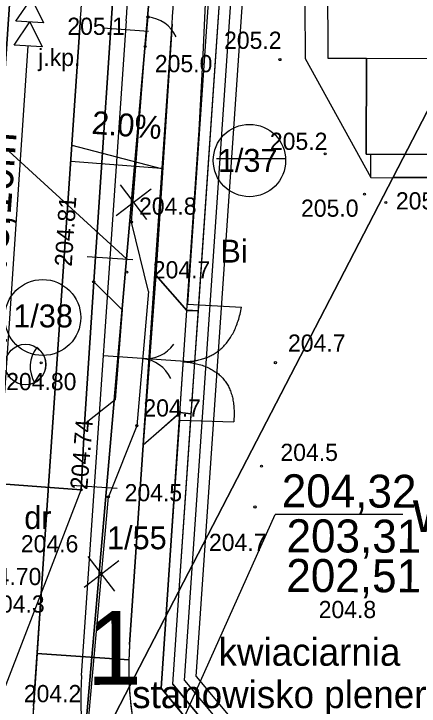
# Model space of a CAD drawing. Extents: x 6512606 to 6513006, y 6022524 to 6022728.
# Drawn here: x 6512732.82 to 6512750.51, y 6022610.86 to 6022641.08 of the extents above; entities that cross this region are included whole.
import ezdxf

# ---------------------------------------------------------------- set-up
doc = ezdxf.new("R2010")
doc.units = 0
for name, color, linetype in [('20', 7, 'Continuous'), ('210-oznaczenie konturu użytku gruntowego', 7, 'Continuous'), ('211-numer działki ewidencyjnej', 7, 'Continuous'), ('217-kontur klasyfikacyjny', 7, 'Continuous'), ('218-kontur użytku gruntowego', 7, 'Continuous'), ('219-działka ewidencyjna', 7, 'Continuous'), ('3', 7, 'Continuous'), ('312-budynek ewidencyjny', 7, 'Continuous'), ('320-blok - kondygnacja nadziemna', 7, 'Continuous'), ('4', 7, 'Continuous'), ('6', 7, 'Continuous'), ('brama (linia)', 7, 'Continuous'), ('brama (linia) - symbol', 7, 'Continuous'), ('Default', 7, 'Continuous'), ('E_OSW_LAMPA', 7, 'Continuous'), ('furtka', 7, 'Continuous'), ('jezdnia', 7, 'Continuous'), ('jezdnia (powierzchnia)', 7, 'Continuous'), ('jezdnia (powierzchnia)-Atr17', 7, 'Continuous'), ('kolor_kostka_bet', 7, 'Continuous'), ('kolor_sc_rowerowa', 7, 'Continuous'), ('Komentarz lub etykieta na mapie', 7, 'Continuous'), ('krawężnik (linia)', 7, 'Continuous'), ('Level 47', 7, 'Continuous'), ('Level 60', 7, 'Continuous'), ('maxp_kan_deszczowa', 7, 'Continuous'), ('maxp_kraw_obniżony', 7, 'Continuous'), ('maxp_krawężnik', 7, 'Continuous'), ('maxp_likwidacje', 7, 'Continuous'), ('maxp_opornik', 7, 'Continuous'), ('maxp_os', 7, 'Continuous'), ('maxp_przechyłki', 7, 'Continuous'), ('maxp_ramka_2', 7, 'Continuous'), ('ogrodzenie', 7, 'Continuous'), ('ogrodzenie trwałe', 7, 'Continuous'), ('ogrodzenie trwałe (linia)', 7, 'Continuous'), ('pikieta naturalna', 7, 'Continuous'), ('pikieta naturalna-Atr2', 7, 'Continuous'), ('pikieta sztuczna', 7, 'Continuous'), ('pikieta sztuczna-Atr2', 7, 'Continuous'), ('przewód kanalizacyjny (linia)', 7, 'Continuous'), ('punkt wysokościowy naturalny', 7, 'Continuous'), ('punkt wysokościowy naturalny-Atr2', 7, 'Continuous'), ('punkt wysokościowy sztuczny', 7, 'Continuous'), ('punkt wysokościowy sztuczny-Atr2', 7, 'Continuous')]:
    doc.layers.add(name, color=color, linetype=linetype)

# ---------------------------------------------------------------- blocks, each defined once
blk = doc.blocks.new('PW01')
at = {"layer": 'Default'}
blk.add_circle((0, 0), 0.45, dxfattribs=at)
blk = doc.blocks.new('OK02')
at = {"layer": 'Default'}
for centre, start, end in [((-15, 0), 0, 60), ((15, 0), 120, 180)]:
    blk.add_arc(centre, 15, start, end, dxfattribs=at)
blk = doc.blocks.new('PW02')
at = {"layer": 'Default'}
blk.add_circle((0, 0), 0.45, dxfattribs=at)
blk = doc.blocks.new('OK04')
at = {"layer": 'Default'}
blk.add_arc((15, 0.01), 15, 120, 180, dxfattribs=at)

msp = doc.modelspace()

# ---------------------------------------------------------------- linework, layer by layer
for p, q in [((6512740.034, 6022615.911), (6512743.337, 6022664.192)), ((6512739.753, 6022611.813), (6512740.034, 6022615.911)), ((6512739.753, 6022611.813), (6512749.181, 6022600.515))]:
    msp.add_line(p, q)
at = {"layer": '20'}
for p in [(6512738.693, 6022606.882), (6512749.792, 6022619.226)]:
    msp.add_line(p, (6512744.215, 6022619.226), dxfattribs=at)
at = {"layer": '217-kontur klasyfikacyjny'}
for points in [[(6512749.37, 6022633.95), (6512735.75, 6022607.64)], [(6512762.09, 6022633.91), (6512749.37, 6022633.95)]]:
    msp.add_lwpolyline(points, dxfattribs=at)
at = {"layer": '218-kontur użytku gruntowego'}
for points in [[(6512739.15, 6022646.62), (6512737.73, 6022630.38)], [(6512737.73, 6022630.38), (6512739.15, 6022646.62)], [(6512749.37, 6022633.95), (6512751.92, 6022638.86)], [(6512751.92, 6022638.86), (6512749.37, 6022633.95)], [(6512731.57, 6022636.01), (6512737.73, 6022630.38)], [(6512737.73, 6022630.38), (6512731.57, 6022636.01)], [(6512735.75, 6022607.64), (6512749.37, 6022633.95)], [(6512749.37, 6022633.95), (6512735.75, 6022607.64)], [(6512762.09, 6022633.91), (6512749.37, 6022633.95)], [(6512749.37, 6022633.95), (6512762.09, 6022633.91)], [(6512737.73, 6022630.38), (6512735.75, 6022607.64)], [(6512735.75, 6022607.64), (6512737.73, 6022630.38)]]:
    msp.add_lwpolyline(points, dxfattribs=at)
at = {"layer": '219-działka ewidencyjna'}
for points in [[(6512739.15, 6022646.62), (6512735.75, 6022607.64)], [(6512751.92, 6022638.86), (6512735.75, 6022607.64)]]:
    msp.add_lwpolyline(points, dxfattribs=at)
at = {"layer": '3'}
msp.add_line((6512741.658, 6022634.756), (6512744.697, 6022634.756), dxfattribs=at)
at = {"layer": '312-budynek ewidencyjny'}
for points in [[(6512746.53, 6022639.13), (6512746.45, 6022659.51)], [(6512748.21, 6022639.13), (6512746.53, 6022639.13)], [(6512748.2, 6022634.95), (6512748.21, 6022639.13)], [(6512759.3, 6022634.91), (6512748.2, 6022634.95)]]:
    msp.add_lwpolyline(points, dxfattribs=at)
at = {"layer": '320-blok - kondygnacja nadziemna'}
msp.add_lwpolyline([(6512759.31, 6022639.09), (6512748.21, 6022639.13), (6512748.2, 6022634.95), (6512759.3, 6022634.91)], close=True, dxfattribs=at)
at = {"layer": '4'}
for points in [[(6512739.15, 6022646.62), (6512735.75, 6022607.64)], [(6512751.92, 6022638.86), (6512735.75, 6022607.64)]]:
    msp.add_lwpolyline(points, dxfattribs=at)
at = {"layer": '6'}
for centre, radius in [((6512743.099, 6022634.675), 1.579), ((6512734.076, 6022627.821), 1.659)]:
    msp.add_circle(centre, radius, dxfattribs=at)
at = {"layer": 'brama (linia)'}
msp.add_lwpolyline([(6512738.69, 6022628.95), (6512738.18, 6022623.1)], dxfattribs=at)
at = {"layer": 'E_OSW_LAMPA'}
msp.add_circle((6512733.326, 6022625.771), 0.885, dxfattribs=at)
for centre, radius, start, end in [((6512734.891, 6022625.665), 1.362, 141.9102, 210.3688), ((6512733.326, 6022625.771), 0.885, 296.1395, 56.1395)]:
    msp.add_arc(centre, radius, start, end, dxfattribs=at)
at = {"layer": 'furtka'}
msp.add_lwpolyline([(6512738.67, 6022640.94), (6512738.55, 6022639.65)], dxfattribs=at)
at = {"layer": 'jezdnia'}
msp.add_lwpolyline([(6512731.08, 6022620.65), (6512728.82, 6022611.46), (6512722.83, 6022600.42), (6512717.94, 6022592.02), (6512712.43, 6022580.37), (6512709.04, 6022573), (6512712.21, 6022570.83), (6512715.01, 6022579.3), (6512720.33, 6022590.74), (6512725.35, 6022598.98), (6512731.85, 6022610.22), (6512735.75, 6022620.3)], close=True, dxfattribs=at)
at = {"layer": 'jezdnia (powierzchnia)'}
msp.add_lwpolyline([(6512732.9, 6022645.58), (6512731.83, 6022629.89), (6512731.08, 6022620.65), (6512735.75, 6022620.3), (6512735.9, 6022623.16), (6512736.3, 6022629.38), (6512737.37, 6022645.25)], dxfattribs=at)
at = {"layer": 'kolor_kostka_bet'}
for p, q in [((6512740.868, 6022628.114), (6512743.337, 6022664.192)), ((6512739.008, 6022629.668), (6512739.72, 6022640.633)), ((6512739.72, 6022640.633), (6512739.008, 6022629.668)), ((6512738.462, 6022622.246), (6512739.008, 6022629.668)), ((6512739.008, 6022629.668), (6512738.462, 6022622.246)), ((6512740.368, 6022628.13), (6512739.008, 6022629.668)), ((6512739.008, 6022629.668), (6512740.368, 6022628.13)), ((6512740.868, 6022628.114), (6512740.368, 6022628.13)), ((6512740.368, 6022628.13), (6512740.868, 6022628.114)), ((6512740.561, 6022623.624), (6512740.868, 6022628.114)), ((6512740.561, 6022623.624), (6512740.868, 6022628.114)), ((6512738.462, 6022622.246), (6512740.064, 6022623.676)), ((6512740.064, 6022623.676), (6512738.462, 6022622.246)), ((6512740.064, 6022623.676), (6512739.241, 6022611.647)), ((6512739.241, 6022611.647), (6512740.064, 6022623.676)), ((6512740.034, 6022615.911), (6512740.561, 6022623.624)), ((6512740.064, 6022623.676), (6512740.561, 6022623.624)), ((6512740.561, 6022623.624), (6512740.064, 6022623.676)), ((6512737.867, 6022613.542), (6512738.462, 6022622.246)), ((6512738.462, 6022622.246), (6512737.867, 6022613.542)), ((6512739.753, 6022611.813), (6512740.034, 6022615.911)), ((6512737.836, 6022612.876), (6512733.831, 6022613.149)), ((6512733.831, 6022613.149), (6512737.836, 6022612.876)), ((6512739.241, 6022611.647), (6512748.908, 6022600.062)), ((6512748.908, 6022600.062), (6512739.241, 6022611.647)), ((6512749.181, 6022600.515), (6512739.753, 6022611.813))]:
    msp.add_line(p, q, dxfattribs=at)
for points in [[(6512735.73, 6022640.906), (6512735.73, 6022640.906), (6512734.114, 6022617.289), (6512733.831, 6022613.149)], [(6512733.831, 6022613.149), (6512733.712, 6022611.416), (6512733.674, 6022610.856)]]:
    msp.add_lwpolyline(points, dxfattribs=at)
for centre, radius, start, end in [((6512687.841, 6022644.182), 48, 356.0866, 2.076), ((6512687.841, 6022644.182), 52, 356.0865, 2.076), ((6512687.841, 6022644.182), 52, 356.0868, 2.076), ((6512752.832, 6022612.518), 15, 176.0865, 257.9783), ((6512752.832, 6022612.518), 15, 176.0865, 178.633), ((6512752.832, 6022612.518), 15, 178.633, 257.9783), ((6512748.639, 6022609.832), 15, 176.0865, 257.9783)]:
    msp.add_arc(centre, radius, start, end, dxfattribs=at)
at = {"layer": 'kolor_sc_rowerowa'}
msp.add_lwpolyline([(6512733.674, 6022610.856), (6512733.712, 6022611.416), (6512733.831, 6022613.149), (6512734.114, 6022617.289), (6512735.73, 6022640.906), (6512735.73, 6022640.906)], dxfattribs=at)
for centre, radius, start, end in [((6512687.841, 6022644.182), 48, 356.0866, 2.076), ((6512748.639, 6022609.832), 15, 176.0865, 185.7922)]:
    msp.add_arc(centre, radius, start, end, dxfattribs=at)
at = {"layer": 'krawężnik (linia)'}
msp.add_lwpolyline([(6512737.37, 6022645.25), (6512736.3, 6022629.38), (6512735.9, 6022623.16), (6512735.75, 6022620.3), (6512731.08, 6022620.65), (6512731.83, 6022629.89), (6512732.9, 6022645.58)], dxfattribs=at)
msp.add_lwpolyline([(6512736.3, 6022629.38), (6512737.54, 6022628.16), (6512737.24, 6022624.23), (6512735.9, 6022623.16)], close=True, dxfattribs=at)
at = {"layer": 'Level 60'}
for points in [[(6512738.696, 6022640.31), (6512736.7, 6022640.447)], [(6512738.013, 6022630.334), (6512736.018, 6022630.47)], [(6512737.331, 6022620.357), (6512735.335, 6022620.493)]]:
    msp.add_lwpolyline(points, dxfattribs=at)
at = {"layer": 'maxp_kan_deszczowa'}
for p, q in [((6512733.512, 6022640.721), (6512733.512, 6022640.722)), ((6512732.109, 6022620.216), (6512733.44, 6022639.674))]:
    msp.add_line(p, q, dxfattribs=at)
msp.add_lwpolyline([(6512748.908, 6022600.062), (6512739.241, 6022611.647), (6512740.368, 6022628.13), (6512740.906, 6022635.995), (6512741.065, 6022638.988), (6512741.55, 6022649.49)], dxfattribs=at)
for points in [[(6512732.907, 6022640.763), (6512733.583, 6022641.769), (6512734.116, 6022640.68)], [(6512732.835, 6022639.716), (6512733.512, 6022640.722), (6512734.045, 6022639.633)]]:
    msp.add_lwpolyline(points, close=True, dxfattribs=at)
at = {"layer": 'maxp_kraw_obniżony'}
msp.add_line((6512738.462, 6022622.246), (6512738.974, 6022629.728), dxfattribs=at)
at = {"layer": 'maxp_krawężnik'}
for p, q in [((6512733.674, 6022610.856), (6512735.73, 6022640.906)), ((6512738.974, 6022629.728), (6512739.72, 6022640.633)), ((6512737.867, 6022613.542), (6512738.462, 6022622.246))]:
    msp.add_line(p, q, dxfattribs=at)
for centre, radius, start, end in [((6512687.841, 6022644.182), 48, 356.0865, 2.076), ((6512687.841, 6022644.182), 52, 356.0865, 2.076), ((6512752.832, 6022612.518), 15, 176.0865, 257.9783), ((6512748.639, 6022609.832), 15, 176.0865, 228.4237)]:
    msp.add_arc(centre, radius, start, end, dxfattribs=at)
at = {"layer": 'maxp_likwidacje'}
for p, q in [((6512737.287, 6022632.277), (6512738.807, 6022633.432)), ((6512738.624, 6022632.094), (6512737.469, 6022633.614)), ((6512737.22, 6022615.872), (6512736.065, 6022617.392)), ((6512735.883, 6022616.055), (6512737.403, 6022617.21))]:
    msp.add_line(p, q, dxfattribs=at)
at = {"layer": 'maxp_opornik'}
for p, q in [((6512740.351, 6022628.149), (6512738.974, 6022629.728)), ((6512740.061, 6022623.64), (6512740.368, 6022628.13)), ((6512740.868, 6022628.114), (6512740.351, 6022628.149)), ((6512740.561, 6022623.624), (6512740.868, 6022628.114)), ((6512740.061, 6022623.64), (6512738.462, 6022622.246)), ((6512740.561, 6022623.624), (6512740.081, 6022623.657))]:
    msp.add_line(p, q, dxfattribs=at)
at = {"layer": 'maxp_os'}
for p, q in [((6512735.77, 6022612.199), (6512737.725, 6022640.769)), ((6512740.715, 6022625.869), (6512736.724, 6022626.142))]:
    msp.add_line(p, q, dxfattribs=at)
for centre, radius, start, end in [((6512687.841, 6022644.182), 50, 356.0868, 2.076), ((6512750.735, 6022611.175), 15, 176.0865, 257.9783)]:
    msp.add_arc(centre, radius, start, end, dxfattribs=at)
at = {"layer": 'maxp_przechyłki'}
msp.add_lwpolyline([(6512735.301, 6022634.639), (6512735.349, 6022635.349), (6512739.252, 6022634.323)], close=True, dxfattribs=at)
at = {"layer": 'maxp_ramka_2'}
for p, q in [((6512740.266, 6022611.979), (6512743.834, 6022664.131)), ((6512740.778, 6022612.146), (6512744.33, 6022664.055)), ((6512740.266, 6022611.979), (6512743.422, 6022658.115)), ((6512740.266, 6022611.979), (6512743.422, 6022658.115)), ((6512740.266, 6022611.979), (6512749.565, 6022600.835)), ((6512740.778, 6022612.146), (6512749.728, 6022601.421))]:
    msp.add_line(p, q, dxfattribs=at)
at = {"layer": 'ogrodzenie'}
for p, q in [((6512742.416, 6022658.054), (6512740.388, 6022628.41)), ((6512740.388, 6022628.41), (6512742.755, 6022628.271)), ((6512740.04, 6022623.334), (6512739.236, 6022611.581)), ((6512740.04, 6022623.334), (6512742.411, 6022623.27)), ((6512739.241, 6022611.647), (6512748.908, 6022600.062))]:
    msp.add_line(p, q, dxfattribs=at)
for points in [[(6512740.218, 6022625.897), (6512742.308, 6022625.904), (6512742.755, 6022628.271)], [(6512740.222, 6022625.892), (6512742.623, 6022625.677), (6512742.411, 6022623.27)]]:
    msp.add_open_spline(points, degree=2, dxfattribs=at)
at = {"layer": 'ogrodzenie trwałe'}
msp.add_lwpolyline([(6512755.94, 6022562.73), (6512746.11, 6022568.85), (6512734.85, 6022575.76), (6512722.94, 6022583.56), (6512729.52, 6022596.18), (6512735.87, 6022607.95), (6512736.94, 6022619.99)], dxfattribs=at)
at = {"layer": 'ogrodzenie trwałe (linia)'}
for points in [[(6512738.67, 6022640.94), (6512739.22, 6022646.99), (6512741.85, 6022657.91), (6512744.36, 6022658.55), (6512746.45, 6022659.08)], [(6512738.69, 6022628.95), (6512737.95, 6022631.99), (6512738.55, 6022639.65)], [(6512738.18, 6022623.1), (6512736.94, 6022619.99)]]:
    msp.add_lwpolyline(points, dxfattribs=at)
at = {"layer": 'przewód kanalizacyjny (linia)'}
for points in [[(6512750.63, 6022659.53), (6512750.53, 6022662.41), (6512746.52, 6022662.45), (6512746.43, 6022659.54), (6512745.45, 6022659.51), (6512745.46, 6022656.91), (6512745.52, 6022641.51), (6512745.53, 6022639.13), (6512748.39, 6022633.94), (6512759.09, 6022633.91), (6512760.48, 6022633.91), (6512760.44, 6022639.05)], [(6512748.39, 6022633.94), (6512748.4, 6022634.94)]]:
    msp.add_lwpolyline(points, dxfattribs=at)

# ---------------------------------------------------------------- block references
at = {"layer": 'brama (linia) - symbol', "xscale": 0.09999999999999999, "yscale": 0.10000000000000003, "rotation": -94.98200000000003}
msp.add_blockref('OK02', (6512738.435, 6022626.025), dxfattribs=at)
at = {"layer": 'furtka', "xscale": 0.1, "yscale": 0.09999999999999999, "rotation": -95.31500000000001}
msp.add_blockref('OK04', (6512738.67, 6022640.94), dxfattribs=at)
at = {"layer": 'pikieta naturalna', "xscale": 0.1, "yscale": 0.10000000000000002}
for p in [(6512738.67, 6022640.94), (6512738.55, 6022639.65), (6512744.43, 6022639.08), (6512746.4, 6022634.97), (6512748.12, 6022633.21), (6512749.05, 6022632.84), (6512744.23, 6022625.85), (6512743.34, 6022619.55), (6512748.86, 6022615.99)]:
    msp.add_blockref('PW01', p, dxfattribs=at)
at = {"layer": 'pikieta sztuczna', "xscale": 0.1, "yscale": 0.10000000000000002}
for p in [(6512734.01, 6022625.84), (6512735.75, 6022620.3)]:
    msp.add_blockref('PW01', p, dxfattribs=at)
at = {"layer": 'punkt wysokościowy naturalny', "xscale": 0.1, "yscale": 0.10000000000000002}
for p in [(6512737.95, 6022631.99), (6512737.74, 6022629.8), (6512738.18, 6022623.1), (6512743.62, 6022621.33), (6512736.94, 6022619.99)]:
    msp.add_blockref('PW01', p, dxfattribs=at)
at = {"layer": 'punkt wysokościowy sztuczny', "xscale": 0.1, "yscale": 0.10000000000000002}
msp.add_blockref('PW02', (6512736.3, 6022629.38), dxfattribs=at)

# ---------------------------------------------------------------- texts
at = {"layer": '210-oznaczenie konturu użytku gruntowego'}
for s, p in [('Bi', (6512741.83, 6022630.22)), ('dr', (6512733.27, 6022618.59))]:
    msp.add_text(s, height=1, dxfattribs=at).set_placement(p)
at = {"layer": '211-numer działki ewidencyjnej'}
for s, p in [('1/37', (6512741.72, 6022634.18)), ('1/38', (6512732.79, 6022627.39)), ('1/55', (6512736.882, 6022617.705))]:
    msp.add_text(s, height=1, dxfattribs=at).set_placement(p)
at = {"layer": '4'}
for s, p in [('1/37', (6512741.72, 6022634.18)), ('1/38', (6512732.79, 6022627.39))]:
    msp.add_text(s, height=1, dxfattribs=at).set_placement(p)
at = {"layer": 'Default'}
msp.add_text('1', height=3.223, rotation=0.1833, dxfattribs=at).set_placement((6512736.002, 6022611.785))
at = {"layer": 'jezdnia (powierzchnia)-Atr17'}
msp.add_text('j.kp.', height=0.75, dxfattribs=at).set_placement((6512733.88, 6022638.8))
at = {"layer": 'Komentarz lub etykieta na mapie'}
for s, p in [('kwiaciarnia ', (6512741.75, 6022612.62)), ('stanowisko plenerowe', (6512737.98, 6022610.77))]:
    msp.add_text(s, height=1.2, dxfattribs=at).set_placement(p)
at = {"layer": 'Level 47'}
for s, height, rotation, p in [('%%c75 PP, L=73,10m', 1.3824, 85.7421, (6512731.768, 6022620.148)), ('204,32', 1.4377, 359.7281, (6512744.504, 6022619.542)), ('wp4', 1.7971, 359.7281, (6512750.229, 6022618.457)), ('203,31', 1.4377, 359.7281, (6512744.714, 6022617.578)), ('202,51', 1.4377, 359.7281, (6512744.705, 6022615.846))]:
    msp.add_text(s, height=height, rotation=rotation, dxfattribs=at).set_placement(p)
at = {"layer": 'maxp_przechyłki'}
msp.add_text('2.0%', height=1, rotation=355.4328, dxfattribs=at).set_placement((6512736.188, 6022635.846))
at = {"layer": 'pikieta naturalna-Atr2'}
for s, p in [('205.1', (6512735.15, 6022640.16)), ('205.2', (6512741.99, 6022639.55)), ('205.0', (6512738.97, 6022638.53)), ('205.2', (6512743.99, 6022635.14)), ('205.0', (6512749.49, 6022632.54)), ('205.0', (6512745.35, 6022632.22)), ('204.7', (6512744.78, 6022626.33)), ('204.7', (6512741.33, 6022617.63)), ('204.3', (6512731.65, 6022614.94)), ('204.8', (6512746.12, 6022614.7)), ('204.2', (6512733.25, 6022611.03))]:
    msp.add_text(s, height=0.75, dxfattribs=at).set_placement(p)
at = {"layer": 'pikieta sztuczna-Atr2'}
for s, p in [('204.80', (6512732.48, 6022624.65)), ('204.70', (6512730.95, 6022616.14))]:
    msp.add_text(s, height=0.75, dxfattribs=at).set_placement(p)
msp.add_text('204.74', height=0.75, rotation=85.36, dxfattribs=at).set_placement((6512736.02, 6022620.28))
at = {"layer": 'punkt wysokościowy naturalny-Atr2'}
for s, p in [('204.8', (6512738.28, 6022632.31)), ('204.7', (6512738.88, 6022629.53)), ('204.7', (6512738.47, 6022623.5)), ('204.5', (6512744.45, 6022621.56)), ('204.5', (6512737.65, 6022619.8)), ('204.6', (6512733.12, 6022617.57))]:
    msp.add_text(s, height=0.75, dxfattribs=at).set_placement(p)
at = {"layer": 'punkt wysokościowy sztuczny-Atr2'}
msp.add_text('204.81', height=0.75, rotation=86.142, dxfattribs=at).set_placement((6512735.34, 6022630.03))

doc.saveas('drawing.dxf')
